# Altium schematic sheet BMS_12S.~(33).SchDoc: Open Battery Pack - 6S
size A3; Author: Morgane Vallée; Revision: 1.0; SheetNumber: 3; SheetTotal: 4
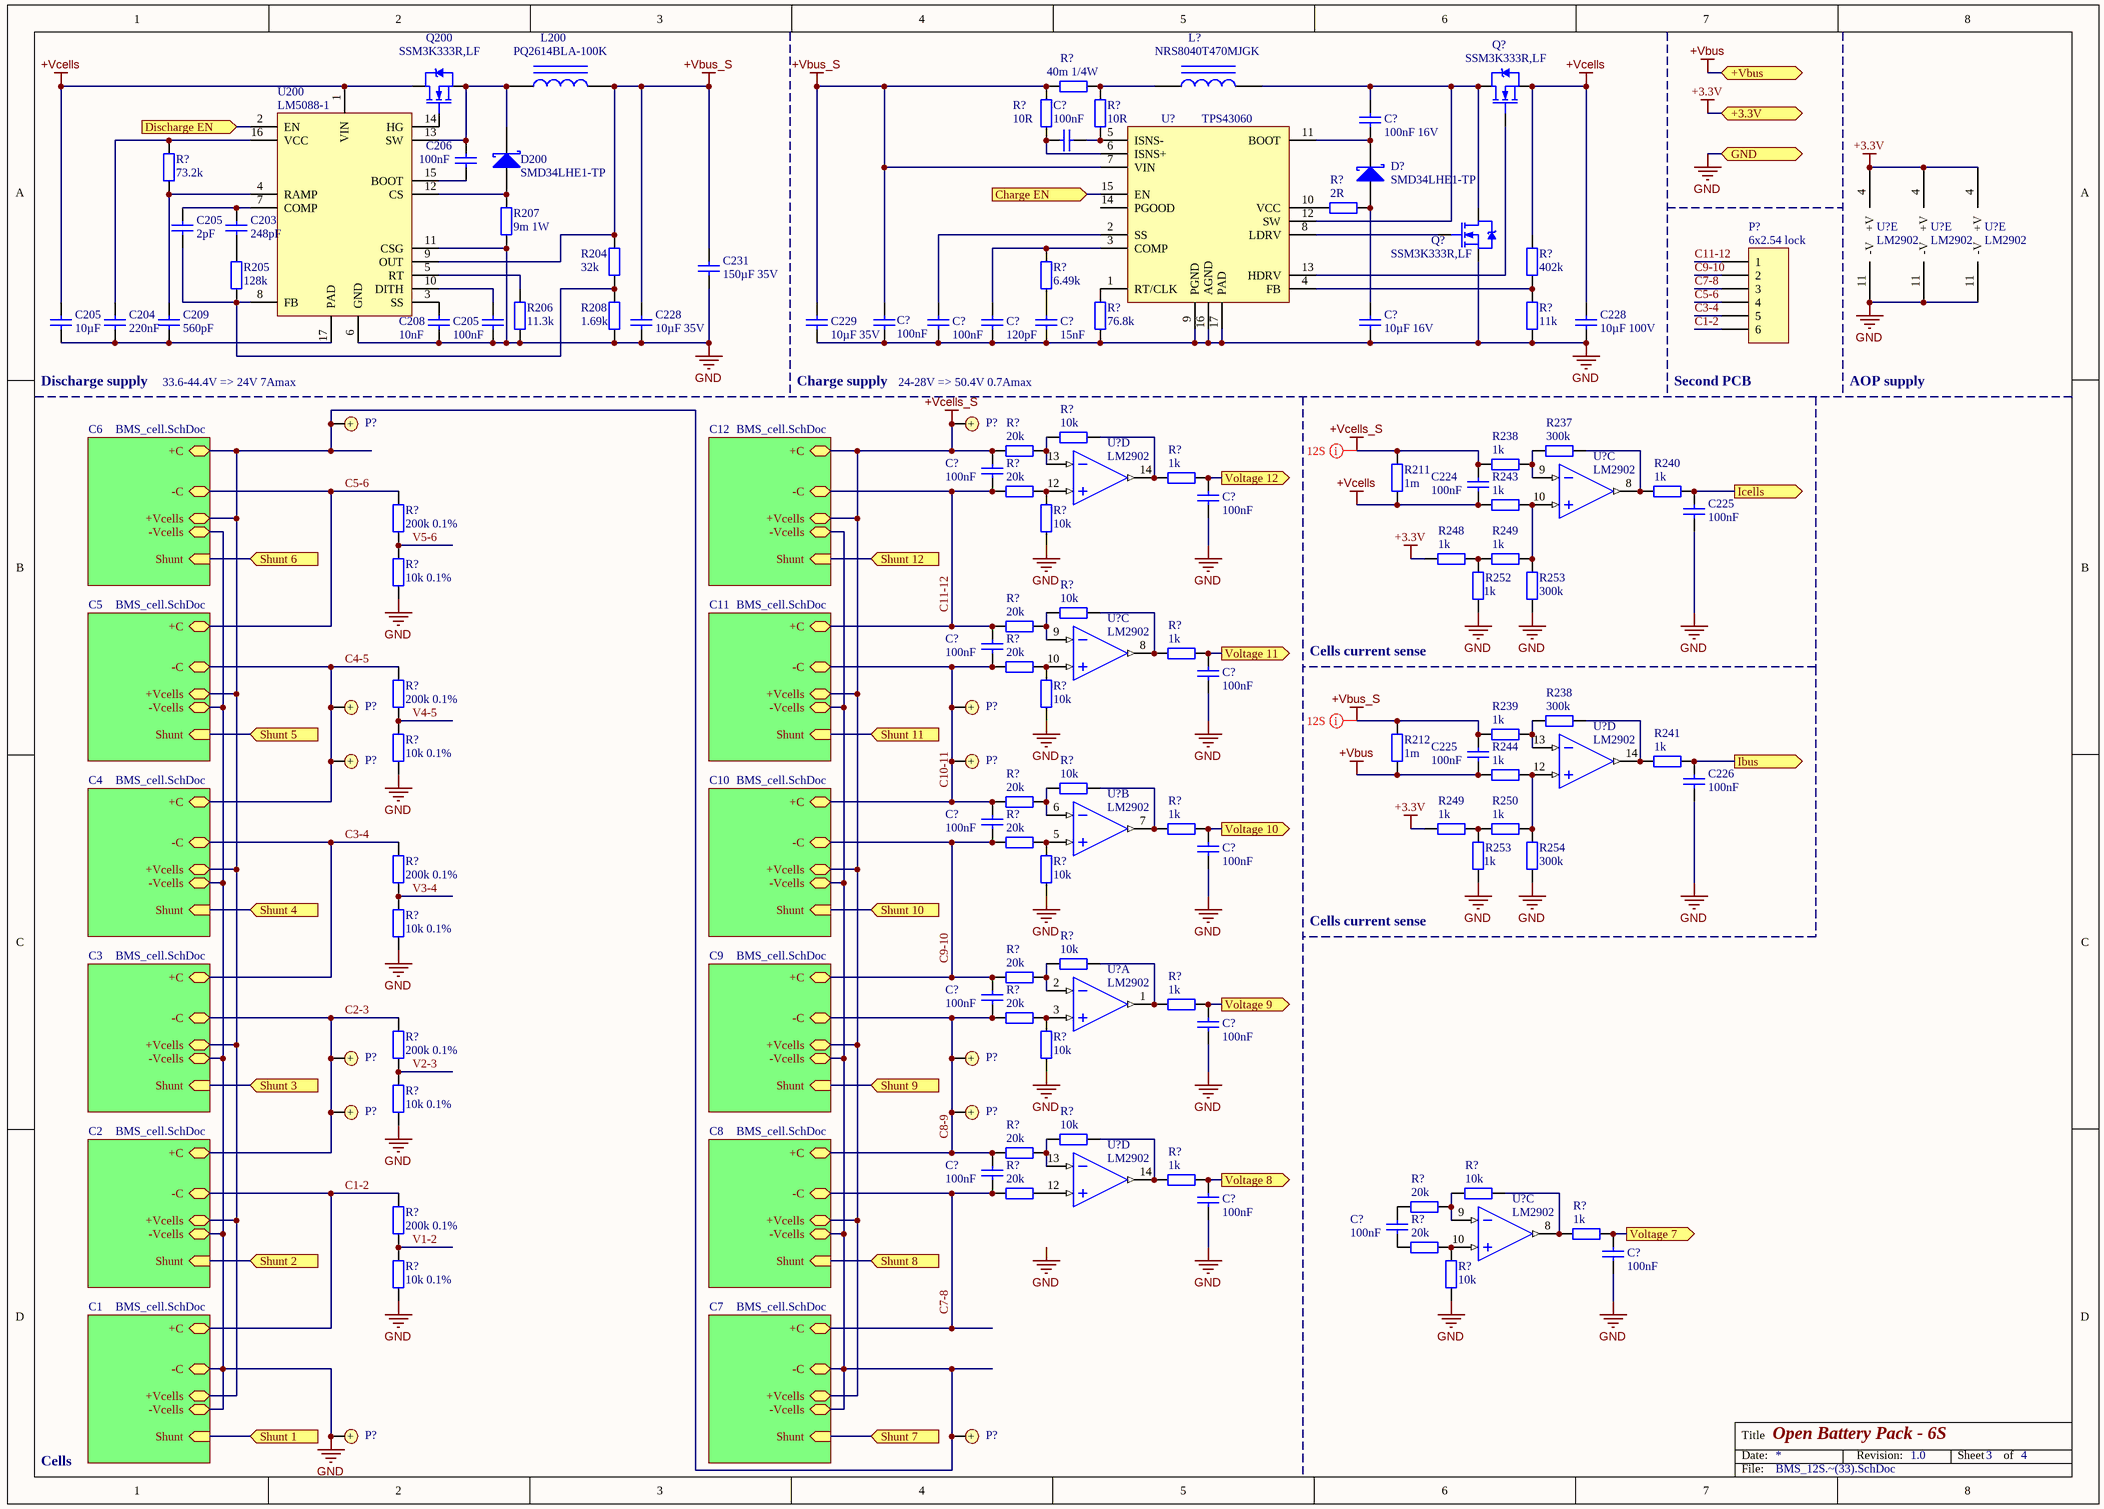
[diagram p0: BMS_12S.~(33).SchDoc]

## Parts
(Parts that share a designator on the sheet are numbered #1, #2 ... from top to bottom, then left to right.)
C203  248pF  [C0603]
C204  220nF  [C0603]
C205#1  2pF  [C0603]
C205#2  10µF  [C0603]
C205#3  100nF  [C0603]
C206  100nF  [C0603]
C208  10nF  [C0603]
C209  560pF  [C0603]
C224  100nF  [C0603]
C225#1  100nF  [C0603]
C225#2  100nF  [C0603]
C226  100nF  [C0603]
C228#1  10µF 35V  [C0603]
C228#2  10µF 100V  [C0603]
C229  10µF 35V  [C0603]
C231  150µF 35V  [C0603]
C?#1  100nF 16V  [C0603]
C?#2  100nF  [C0603]
C?#3  100nF  [C0603]
C?#4  120pF  [C0603]
C?#5  15nF  [C0603]
C?#6  10µF 16V  [C0805]
C?#7  100nF  [C0603]
C?#8  100nF  [C0603]
C?#9  100nF  [C0603]
C?#10  100nF  [C0603]
C?#11  100nF  [C0603]
C?#12  100nF  [C0603]
C?#13  100nF  [C0603]
C?#14  100nF  [C0603]
C?#15  100nF  [C0603]
C?#16  100nF  [C0603]
C?#17  100nF  [C0603]
C?#18  100nF  [C0603]
C?#19  100nF  [C0603]
D200  SMD34LHE1-TP  [SOD-123H]
D?  SMD34LHE1-TP  [SOD-123H]
L200  PQ2614BLA-100K  [SELF_SMD_8x8]
L?  NRS8040T470MJGK  [SELF_SMD_8x8]
P?#1  6x2.54 lock  [MOLEX KK 0022272061]
P?#2  Bat+  [Keystone 241]  (value not drawn)
P?#3  Bat+  [Keystone 241]  (value not drawn)
P?#4  Bat+  [Keystone 241]  (value not drawn)
P?#5  Bat+  [Keystone 241]  (value not drawn)
P?#6  Bat+  [Keystone 241]  (value not drawn)
P?#7  Bat+  [Keystone 241]  (value not drawn)
P?#8  Bat+  [Keystone 241]  (value not drawn)
P?#9  Bat+  [Keystone 241]  (value not drawn)
P?#10  Bat+  [Keystone 241]  (value not drawn)
P?#11  Bat+  [Keystone 241]  (value not drawn)
P?#12  Bat+  [Keystone 241]  (value not drawn)
P?#13  Bat+  [Keystone 241]  (value not drawn)
Q200  SSM3K333R,LF  [TI SOT-23-3 DBZ]
Q?#1  SSM3K333R,LF  [TI SOT-23-3 DBZ]
Q?#2  SSM3K333R,LF  [TI SOT-23-3 DBZ]
R204  32k  [R0603]
R205  128k  [R0603]
R206  11.3k  [R0603]
R207  9m 1W  [R1206]
R208  1.69k  [R0603]
R211  1m  [R1206]
R212  1m  [R1206]
R237  300k  [R0603]
R238#1  1k  [R0603]
R238#2  300k  [R0603]
R239  1k  [R0603]
R240  1k  [R0603]
R241  1k  [R0603]
R243  1k  [R0603]
R244  1k  [R0603]
R248  1k  [R0603]
R249#1  1k  [R0603]
R249#2  1k  [R0603]
R250  1k  [R0603]
R252  1k  [R0603]
R253#1  300k  [R0603]
R253#2  1k  [R0603]
R254  300k  [R0603]
R?#1  10R  [R0603]
R?#2  40m 1/4W  [R1206]
R?#3  10R  [R0603]
R?#4  73.2k  [R0603]
R?#5  2R  [R0603]
R?#6  402k  [R0603]
R?#7  6.49k  [R0603]
R?#8  76.8k  [R0603]
R?#9  11k  [R0603]
R?#10  10k  [R0603]
R?#11  20k  [R0603]
R?#12  1k  [R0603]
R?#13  200k 0.1%  [R0603]
R?#14  20k  [R0603]
R?#15  10k  [R0603]
R?#16  10k 0.1%  [R0603]
R?#17  10k  [R0603]
R?#18  20k  [R0603]
R?#19  1k  [R0603]
R?#20  200k 0.1%  [R0603]
R?#21  20k  [R0603]
R?#22  10k  [R0603]
R?#23  10k 0.1%  [R0603]
R?#24  10k  [R0603]
R?#25  20k  [R0603]
R?#26  1k  [R0603]
R?#27  200k 0.1%  [R0603]
R?#28  20k  [R0603]
R?#29  10k  [R0603]
R?#30  10k 0.1%  [R0603]
R?#31  10k  [R0603]
R?#32  20k  [R0603]
R?#33  1k  [R0603]
R?#34  200k 0.1%  [R0603]
R?#35  20k  [R0603]
R?#36  10k  [R0603]
R?#37  10k 0.1%  [R0603]
R?#38  10k  [R0603]
R?#39  20k  [R0603]
R?#40  10k  [R0603]
R?#41  1k  [R0603]
R?#42  20k  [R0603]
R?#43  200k 0.1%  [R0603]
R?#44  20k  [R0603]
R?#45  1k  [R0603]
R?#46  10k 0.1%  [R0603]
R?#47  20k  [R0603]
R?#48  10k  [R0603]
U200  LM5088-1  [TI MSOP-10 DGQ]
U?#1  TPS43060  [TI WQFN-16 RGH]
U?#2  LM2902  [Atmel SO-14 14S1]  (part E of 5)
U?#3  LM2902  [Atmel SO-14 14S1]  (part E of 5)
U?#4  LM2902  [Atmel SO-14 14S1]  (part E of 5)
U?#5  LM2902  [Atmel SO-14 14S1]  (part D of 5)
U?#6  LM2902  [Atmel SO-14 14S1]  (part C of 5)
U?#7  LM2902  [Atmel SO-14 14S1]  (part C of 5)
U?#8  LM2902  [Atmel SO-14 14S1]  (part D of 5)
U?#9  LM2902  [Atmel SO-14 14S1]  (part B of 5)
U?#10  LM2902  [Atmel SO-14 14S1]  (part A of 5)
U?#11  LM2902  [Atmel SO-14 14S1]  (part D of 5)
U?#12  LM2902  [Atmel SO-14 14S1]  (part C of 5)

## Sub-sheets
C1 = BMS_cell.SchDoc: -C, +C, +Vcells, -Vcells, Shunt (in)
C2 = BMS_cell.SchDoc: -C, +C, +Vcells, -Vcells, Shunt (in)
C3 = BMS_cell.SchDoc: -C, +C, +Vcells, -Vcells, Shunt (in)
C4 = BMS_cell.SchDoc: -C, +C, +Vcells, -Vcells, Shunt (in)
C5 = BMS_cell.SchDoc: -C, +C, +Vcells, -Vcells, Shunt (in)
C6 = BMS_cell.SchDoc: -C, +C, +Vcells, -Vcells, Shunt (in)
C7 = BMS_cell.SchDoc: -C, +C, +Vcells, -Vcells, Shunt (in)
C8 = BMS_cell.SchDoc: -C, +C, +Vcells, -Vcells, Shunt (in)
C9 = BMS_cell.SchDoc: -C, +C, +Vcells, -Vcells, Shunt (in)
C10 = BMS_cell.SchDoc: -C, +C, +Vcells, -Vcells, Shunt (in)
C11 = BMS_cell.SchDoc: -C, +C, +Vcells, -Vcells, Shunt (in)
C12 = BMS_cell.SchDoc: -C, +C, +Vcells, -Vcells, Shunt (in)

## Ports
+3.3V, +Vbus, Charge EN (in), Discharge EN (in), GND, Ibus (out), Icells (out), Shunt 1 (in), Shunt 2 (in), Shunt 3 (in), Shunt 4 (in), Shunt 5 (in), Shunt 6 (in), Shunt 7 (in), Shunt 8 (in), Shunt 9 (in), Shunt 10 (in), Shunt 11 (in), Shunt 12 (in), Voltage 7 (out), Voltage 8 (out), Voltage 9 (out), Voltage 10 (out), Voltage 11 (out), Voltage 12 (out)

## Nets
+3.3V: R248.2 R249#2.2 U?#2.4(+V) U?#3.4(+V) U?#4.4(+V) ; port +3.3V
+Vbus: C225#2.2 R212.1 R244.2 ; port +Vbus
+Vbus_S: C225#2.1 C228#1.1 C229.1 C231.1 C?#7.2 L200.2 R204.2 R212.2 R239.1 R?#1.1 R?#2.2 U200.9(OUT) U?#1.7(VIN)
+Vcells: C205#2.1 C224.2 C228#2.1 Q200.3(D) Q?#1.2(S) R211.1 R243.2 R?#6.2 U200.1(VIN)
+Vcells_S: C224.1 C?#8.1 P?#3.1 R211.2 R238#1.1 R?#11.1 ; sheet C7/+Vcells, sheet C8/+Vcells, sheet C9/+Vcells, sheet C10/+Vcells, sheet C11/+Vcells, sheet C12/+C, sheet C12/+Vcells
GND: C205#3.2 C208.2 C225#1.2 C226.2 C228#1.2 C228#2.2 C229.2 C231.2 C?#3.2 C?#4.2 C?#5.2 C?#6.2 C?#7.1 C?#9.2 C?#11.2 C?#13.2 C?#15.2 C?#17.2 C?#19.2 P?#12.1 Q?#2.2(S) R206.1 R207.1 R208.1 R252.2 R253#1.1 R253#2.2 R254.1 R?#8.1 R?#9.1 R?#15.2 R?#16.2 R?#22.2 R?#23.2 R?#29.2 R?#30.2 R?#36.2 R?#37.2 R?#46.2 R?#48.2 U200.6(GND) U200.11(CSG) U?#1.9(PGND) U?#1.16(AGND) U?#1.17(PAD) U?#2.11(-V) U?#3.11(-V) U?#4.11(-V) ; port GND, sheet C1/-C, sheet C1/-Vcells, sheet C2/-Vcells, sheet C3/-Vcells, sheet C4/-Vcells, sheet C5/-Vcells, sheet C6/-Vcells
C1-2: P?#1.6 R?#43.1 ; sheet C1/+C, sheet C2/-C
C2-3: P?#8.1 P?#10.1 R?#34.1 ; sheet C2/+C, sheet C3/-C
C3-4: P?#1.5 R?#27.1 ; sheet C3/+C, sheet C4/-C
C4-5: P?#4.1 P?#6.1 R?#20.1 ; sheet C4/+C, sheet C5/-C
C5-6: P?#1.4 R?#13.1 ; sheet C5/+C, sheet C6/-C
C7-8: C?#16.2 P?#1.3 R?#44.2 ; sheet C7/+C, sheet C8/-C
C8-9: C?#14.2 C?#16.1 P?#9.1 P?#11.1 R?#35.2 R?#39.1 ; sheet C8/+C, sheet C9/-C
C9-10: C?#12.2 C?#14.1 P?#1.2 R?#28.2 R?#32.1 ; sheet C9/+C, sheet C10/-C
C10-11: C?#10.2 C?#12.1 P?#5.1 P?#7.1 R?#21.2 R?#25.1 ; sheet C10/+C, sheet C11/-C
C11-12: C?#8.2 C?#10.1 P?#1.1 R?#14.2 R?#18.1 ; sheet C11/+C, sheet C12/-C
Charge EN: U?#1.15(EN) ; port Charge EN
Discharge EN: U200.2(EN) ; port Discharge EN
Ibus: C226.1 R241.1 ; port Ibus
Icells: C225#1.1 R240.1 ; port Icells
Shunt 1: port Shunt 1, sheet C1/Shunt
Shunt 2: port Shunt 2, sheet C2/Shunt
Shunt 3: port Shunt 3, sheet C3/Shunt
Shunt 4: port Shunt 4, sheet C4/Shunt
Shunt 5: port Shunt 5, sheet C5/Shunt
Shunt 6: port Shunt 6, sheet C6/Shunt
Shunt 7: port Shunt 7, sheet C7/Shunt
Shunt 8: port Shunt 8, sheet C8/Shunt
Shunt 9: port Shunt 9, sheet C9/Shunt
Shunt 10: port Shunt 10, sheet C10/Shunt
Shunt 11: port Shunt 11, sheet C11/Shunt
Shunt 12: port Shunt 12, sheet C12/Shunt
V1-2: R?#43.2 R?#46.1
V2-3: R?#34.2 R?#37.1
V3-4: R?#27.2 R?#30.1
V4-5: R?#20.2 R?#23.1
V5-6: R?#13.2 R?#16.1
Voltage 7: C?#19.1 R?#45.1 ; port Voltage 7
Voltage 8: C?#17.1 R?#41.1 ; port Voltage 8
Voltage 9: C?#15.1 R?#33.1 ; port Voltage 9
Voltage 10: C?#13.1 R?#26.1 ; port Voltage 10
Voltage 11: C?#11.1 R?#19.1 ; port Voltage 11
Voltage 12: C?#9.1 R?#12.1 ; port Voltage 12
NetC203_1: C203.1 C205#1.1 U200.7(COMP)
NetC203_2: C203.2 R205.2
NetC204_1: C204.1 R?#4.2 U200.16(VCC)
NetC204_2: C204.2 C205#2.2 C209.2 U200.17(PAD)
NetC205#1_2: C205#1.2 R204.1 R205.1 R208.2 U200.8(FB)
NetC205#3_1: C205#3.1 U200.10(DITH)
NetC206_1: C206.1 D200.3(K) L200.1 Q200.2(S) U200.13(SW)
NetC206_2: C206.2 U200.15(BOOT)
NetC208_1: C208.1 U200.3(SS)
NetC209_1: C209.1 R?#4.1 U200.4(RAMP)
NetC?#1_1: C?#1.1 L?.2 Q?#1.3(D) Q?#2.3(D) U?#1.12(SW)
NetC?#1_2: C?#1.2 D?.3(K) U?#1.11(BOOT)
NetC?#2_1: C?#2.1 R?#3.2 U?#1.5(ISNS-)
NetC?#2_2: C?#2.2 R?#1.2 U?#1.6(ISNS+)
NetC?#3_1: C?#3.1 U?#1.2(SS)
NetC?#4_1: C?#4.1 R?#7.2 U?#1.3(COMP)
NetC?#5_1: C?#5.1 R?#7.1
NetC?#6_1: C?#6.1 D?.1(A) R?#5.1
NetC?#18_1: C?#18.1 R?#42.1
NetC?#18_2: C?#18.2 R?#47.2
NetD200_1: D200.1(A) R207.2 U200.12(CS)
NetL?_1: L?.1 R?#2.1 R?#3.1
NetP?#2_1: P?#2.1 P?#13.1 ; sheet C1/+Vcells, sheet C2/+Vcells, sheet C3/+Vcells, sheet C4/+Vcells, sheet C5/+Vcells, sheet C6/+C, sheet C6/+Vcells, sheet C7/-C, sheet C7/-Vcells, sheet C8/-Vcells, sheet C9/-Vcells, sheet C10/-Vcells, sheet C11/-Vcells, sheet C12/-Vcells
NetQ200_1: Q200.1(G) U200.14(HG)
NetQ?#1_1: Q?#1.1(G) U?#1.13(HDRV)
NetQ?#2_1: Q?#2.1(G) U?#1.8(LDRV)
NetR206_2: R206.2 U200.5(RT)
NetR237_1: R237.1 R240.2 U?#6.8(OUT)
NetR237_2: R237.2 R238#1.2 U?#6.9(IN-)
NetR238#2_1: R238#2.1 R241.2 U?#8.14(OUT)
NetR238#2_2: R238#2.2 R239.2 U?#8.13(IN-)
NetR243_1: R243.1 R249#1.1 R253#1.2 U?#6.10(IN+)
NetR244_1: R244.1 R250.1 R254.2 U?#8.12(IN+)
NetR248_1: R248.1 R249#1.2 R252.1
NetR249#2_1: R249#2.1 R250.2 R253#2.1
NetR?#5_2: R?#5.2 U?#1.10(VCC)
NetR?#6_1: R?#6.1 R?#9.2 U?#1.4(FB)
NetR?#8_2: R?#8.2 U?#1.1(RT/CLK)
NetR?#10_1: R?#10.1 R?#11.2 U?#5.13(IN-)
NetR?#10_2: R?#10.2 R?#12.2 U?#5.14(OUT)
NetR?#14_1: R?#14.1 R?#15.1 U?#5.12(IN+)
NetR?#17_1: R?#17.1 R?#18.2 U?#7.9(IN-)
NetR?#17_2: R?#17.2 R?#19.2 U?#7.8(OUT)
NetR?#21_1: R?#21.1 R?#22.1 U?#7.10(IN+)
NetR?#24_1: R?#24.1 R?#25.2 U?#9.6(IN-)
NetR?#24_2: R?#24.2 R?#26.2 U?#9.7(OUT)
NetR?#28_1: R?#28.1 R?#29.1 U?#9.5(IN+)
NetR?#31_1: R?#31.1 R?#32.2 U?#10.2(IN-)
NetR?#31_2: R?#31.2 R?#33.2 U?#10.1(OUT)
NetR?#35_1: R?#35.1 R?#36.1 U?#10.3(IN+)
NetR?#38_1: R?#38.1 R?#39.2 U?#11.13(IN-)
NetR?#38_2: R?#38.2 R?#41.2 U?#11.14(OUT)
NetR?#40_1: R?#40.1 R?#42.2 U?#12.9(IN-)
NetR?#40_2: R?#40.2 R?#45.2 U?#12.8(OUT)
NetR?#44_1: R?#44.1 U?#11.12(IN+)
NetR?#47_1: R?#47.1 R?#48.1 U?#12.10(IN+)

Not connected (* = marked no-connect by the designer): U?#1 14(PGOOD)

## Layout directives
net class 12S: +Vbus_S, +Vcells_S

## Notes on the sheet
- Discharge supply
- 33.6-44.4V => 24V 7Amax
- Charge supply
- 24-28V => 50.4V 0.7Amax
- (near P?#1) Second PCB
- AOP supply
- Cells current sense
- (near R253#2) Cells current sense
- Cells
- Labels drawn without touching a wire or pin: GND

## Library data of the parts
C203 C204 C205#1-C205#3 C206 C208 C209 C224 C225#1 C225#2 C226 C228#1 C228#2 C229 C231 C?#1-C?#19 = Cap: Capacitor
D200 D? = Diode BAT17
L200 L? = Inductor Iron: Magnetic-Core Inductor
P?#1 = Header 6: Header, 6-Pin
P?#2-P?#13 = Bat+: Battery contact +
Q200 Q?#1 Q?#2 = MOSFET_N
R204-R208 R211 R212 R237 R238#1 R238#2 R239-R241 R243 R244 R248 R249#1 R249#2 R250 R252 R253#1 R253#2 R254 R?#1-R?#48 = Res2: Resistor
U200 = LM5088-1: Wide Input Range Non-Synchronous Buck Controller
U?#1 = TPS43060: Low Quiescent Current Synchronous Boost  DC-DC Controller With Wide VIN Range
U?#2-U?#12 = LM2902: Low-power quad operational amplifiers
